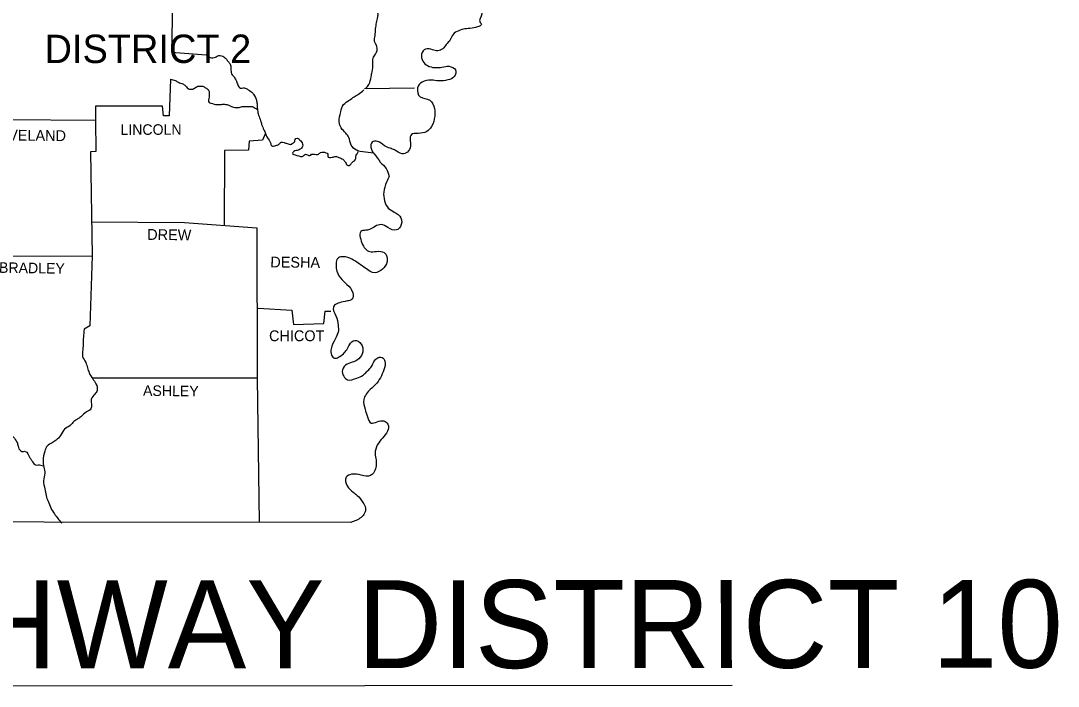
# Model space of a CAD drawing. Extents: x 2520745 to 2582119, y -1491628 to -1461664.
# Drawn here: x 2561979 to 2568174, y -1472575 to -1468600 of the extents above; entities that cross this region are included whole.
import ezdxf

# ---------------------------------------------------------------- set-up
doc = ezdxf.new("R2010")
doc.units = 0
doc.layers.add('R_Draft', color=7, linetype='Continuous')

msp = doc.modelspace()

# ---------------------------------------------------------------- linework, layer by layer
at = {"layer": 'R_Draft'}
for p, q in [((2564031, -1469004.7), (2564331, -1469000)), ((2563384.5, -1469125.1), (2563393.1, -1469130)), ((2564085.2, -1469391.7), (2563990.7, -1469379.7)), ((2556309, -1472574.9), (2566227.4, -1472568.9))]:
    msp.add_line(p, q, dxfattribs=at)
for points in [[(2562891, -1468199.2), (2562878.8, -1468787.9), (2563087.3, -1468804.3)], [(2562874.4, -1468948.4), (2562865.6, -1469168.9), (2562831.1, -1469168.9), (2562825, -1469110.4), (2562426, -1469110.7), (2562426.1, -1469194.7)], [(2561892.1, -1469190.5), (2562423.1, -1469193.2)], [(2562426.1, -1469193.2), (2562427.7, -1469380.7), (2562396.2, -1469382.2), (2562405.6, -1470004.7)], [(2563440.1, -1469272.1), (2563422.1, -1469312.6), (2563342.6, -1469320.1), (2563338.2, -1469374.1), (2563195.7, -1469374.2), (2563194.5, -1469822.8)], [(2562400.9, -1469800.7), (2562957.4, -1469804.9), (2563389.5, -1469837.6)], [(2563389.5, -1469837.6), (2563390, -1470734.6), (2563402.5, -1471597.1)], [(2561727.6, -1470006.6), (2562405.6, -1470004.7)], [(2562405.6, -1470004.7), (2562390.8, -1470421.7), (2562357.8, -1470442.7)], [(2563397.3, -1470316.1), (2563598.3, -1470328), (2563607.3, -1470415), (2563788.8, -1470408.9), (2563796.3, -1470335.4), (2563830.8, -1470335.3)], [(2563950, -1471596.8), (2558452.5, -1471591.1), (2558448.8, -1470377.6)], [(2562405.4, -1470733.7), (2563390, -1470733.1)]]:
    msp.add_lwpolyline(points, dxfattribs=at)
for points in [[(2565210.6, -1467544.5), (2565176.1, -1467588), (2565125.1, -1467561), (2565125.1, -1467525), (2565132.5, -1467487.5), (2565114.5, -1467463.5), (2565083, -1467474.1), (2565083.1, -1467520.6), (2565080.1, -1467565.6), (2565071.1, -1467630.1), (2565092.1, -1467649.6), (2565140.1, -1467655.5), (2565174.6, -1467664.5), (2565195.7, -1467699), (2565194.2, -1467741), (2565177.7, -1467781.5), (2565153.7, -1467814.5), (2565116.2, -1467826.5), (2565086.2, -1467807.1), (2565074.2, -1467768.1), (2565060.7, -1467733.6), (2565035.2, -1467708.1), (2565008.2, -1467736.6), (2565002.2, -1467789.1), (2565003.7, -1467834.1), (2565003.8, -1467895.6), (2565042.8, -1467936.1), (2565066.8, -1467982.6), (2565059.4, -1468024.6), (2565030.9, -1468074.1), (2565018.9, -1468117.6), (2565007, -1468176.1), (2565008.5, -1468240.6), (2564998, -1468303.6), (2564977.1, -1468345.6), (2564938.1, -1468380.2), (2564912.6, -1468402.7), (2564891.6, -1468425.2), (2564881.1, -1468470.2), (2564873.7, -1468501.7), (2564845.2, -1468539.2), (2564822.7, -1468542.2), (2564804.7, -1468527.2), (2564798.7, -1468501.7), (2564798.6, -1468476.2), (2564786.6, -1468450.7), (2564749.1, -1468440.3), (2564719.1, -1468441.8), (2564705.6, -1468462.8), (2564725.2, -1468521.3), (2564732.7, -1468558.8), (2564722.2, -1468609.8), (2564728.2, -1468615.8), (2564674.2, -1468644.3), (2564630.7, -1468648.8), (2564594.7, -1468659.4), (2564560.3, -1468681.9), (2564543.8, -1468714.9), (2564519.8, -1468741.9), (2564498.8, -1468767.4), (2564470.3, -1468779.4), (2564438.8, -1468773.5), (2564396.8, -1468769), (2564372.8, -1468799), (2564380.4, -1468842.5), (2564408.9, -1468868), (2564450.9, -1468880), (2564494.4, -1468876.9), (2564536.4, -1468872.4), (2564575.4, -1468893.4), (2564567.9, -1468933.9), (2564530.4, -1468953.4), (2564474.9, -1468959.4), (2564429.9, -1468955), (2564375.9, -1468967), (2564349, -1469001.5), (2564364, -1469054), (2564422.5, -1469075), (2564449.5, -1469124.5), (2564451.1, -1469171), (2564431.6, -1469232.5), (2564404.6, -1469261), (2564352.1, -1469273), (2564311.6, -1469280.5), (2564305.7, -1469349.5), (2564287.7, -1469384.1), (2564256.2, -1469394.6), (2564211.2, -1469372.1), (2564184.2, -1469361.6), (2564151.2, -1469346.6), (2564109.1, -1469321.2), (2564077.7, -1469325.7), (2564086.7, -1469391.7), (2564089.7, -1469394.7), (2564125.7, -1469444.2), (2564161.7, -1469483.1), (2564178.3, -1469529.6)], [(2565210.6, -1467544.5), (2565176.1, -1467588), (2565125.1, -1467561), (2565125.1, -1467525), (2565132.5, -1467487.5), (2565114.5, -1467463.5), (2565083, -1467474.1), (2565083.1, -1467520.6), (2565080.1, -1467565.6), (2565071.1, -1467630.1), (2565092.1, -1467649.6), (2565140.1, -1467655.5), (2565174.6, -1467664.5), (2565195.7, -1467699), (2565194.2, -1467741), (2565177.7, -1467781.5), (2565153.7, -1467814.5), (2565116.2, -1467826.5), (2565086.2, -1467807.1), (2565074.2, -1467768.1), (2565060.7, -1467733.6), (2565035.2, -1467708.1), (2565008.2, -1467736.6), (2565002.2, -1467789.1), (2565003.7, -1467834.1), (2565003.8, -1467895.6), (2565042.8, -1467936.1), (2565066.8, -1467982.6), (2565059.4, -1468024.6), (2565030.9, -1468074.1), (2565018.9, -1468117.6), (2565007, -1468176.1), (2565008.5, -1468240.6), (2564998, -1468303.6), (2564977.1, -1468345.6), (2564938.1, -1468380.2), (2564912.6, -1468402.7), (2564891.6, -1468425.2), (2564881.1, -1468470.2), (2564873.7, -1468501.7), (2564845.2, -1468539.2), (2564822.7, -1468542.2), (2564804.7, -1468527.2), (2564798.7, -1468501.7), (2564798.6, -1468476.2), (2564786.6, -1468450.7), (2564749.1, -1468440.3), (2564719.1, -1468441.8), (2564705.6, -1468462.8), (2564725.2, -1468521.3), (2564732.7, -1468558.8), (2564722.2, -1468609.8), (2564728.2, -1468615.8), (2564674.2, -1468644.3), (2564630.7, -1468648.8), (2564594.7, -1468659.4), (2564560.3, -1468681.9), (2564543.8, -1468714.9), (2564519.8, -1468741.9), (2564498.8, -1468767.4), (2564470.3, -1468779.4), (2564438.8, -1468773.5), (2564396.8, -1468769), (2564372.8, -1468799), (2564380.4, -1468842.5), (2564408.9, -1468868), (2564450.9, -1468880), (2564494.4, -1468876.9), (2564536.4, -1468872.4), (2564575.4, -1468893.4), (2564567.9, -1468933.9), (2564530.4, -1468953.4), (2564474.9, -1468959.4), (2564429.9, -1468955), (2564375.9, -1468967), (2564349, -1469001.5), (2564364, -1469054), (2564422.5, -1469075), (2564449.5, -1469124.5), (2564451.1, -1469171), (2564431.6, -1469232.5), (2564404.6, -1469261), (2564352.1, -1469273), (2564311.6, -1469280.5), (2564305.7, -1469349.5), (2564287.7, -1469384.1), (2564256.2, -1469394.6), (2564211.2, -1469372.1), (2564184.2, -1469361.6), (2564151.2, -1469346.6), (2564109.1, -1469321.2), (2564077.7, -1469325.7), (2564086.7, -1469391.7), (2564089.7, -1469394.7), (2564125.7, -1469444.2), (2564161.7, -1469483.1), (2564178.3, -1469529.6)], [(2564038.5, -1469004.7), (2564057.9, -1468980.7), (2564071.4, -1468934.2), (2564077.4, -1468905.7), (2564081.9, -1468856.2), (2564083.3, -1468823.2), (2564098.3, -1468799.2), (2564105.8, -1468754.2), (2564092.3, -1468724.2), (2564095.3, -1468688.2), (2564098.2, -1468647.7), (2564104.2, -1468611.7), (2564111.7, -1468577.2), (2564111.7, -1468554.7), (2564092.2, -1468524.7), (2564062.2, -1468505.2), (2564038.1, -1468497.7), (2564023.1, -1468487.2), (2564002.1, -1468469.2), (2563981.1, -1468433.2), (2563969.1, -1468419.7), (2563945.1, -1468388.3), (2563921.1, -1468370.3), (2563906, -1468329.8), (2563882, -1468301.3), (2563849, -1468289.3), (2563825, -1468263.8), (2563816, -1468224.8), (2563801, -1468200.8), (2563780, -1468185.9), (2563745.4, -1468164.9), (2563719.9, -1468149.9), (2563712.4, -1468115.4), (2563697.4, -1468098.9), (2563661.4, -1468089.9), (2563656.9, -1468028.4)], [(2563087.3, -1468804.3), (2563109.8, -1468819.3), (2563141.3, -1468817.8), (2563162.3, -1468808.7), (2563178.8, -1468810.2), (2563201.3, -1468823.7), (2563216.4, -1468841.7), (2563226.9, -1468855.2), (2563234.4, -1468876.2), (2563234.4, -1468895.7), (2563241.9, -1468922.7), (2563250.9, -1468933.2), (2563262.9, -1468952.7), (2563270.4, -1468970.7), (2563274.9, -1468982.7), (2563291.5, -1469002.2), (2563306.5, -1469000.7), (2563320, -1469002.1), (2563338, -1469012.6), (2563365, -1469033.6), (2563369.5, -1469039.6), (2563387.5, -1469078.6), (2563390.5, -1469102.6), (2563393.5, -1469134.1), (2563399.6, -1469164.1), (2563411.6, -1469197.1), (2563417.6, -1469219.6), (2563431.1, -1469251.1), (2563440.1, -1469272.1), (2563452.1, -1469299.1), (2563470.2, -1469329.1), (2563477.7, -1469347), (2563503.2, -1469345.5), (2563521.2, -1469338), (2563534.7, -1469326), (2563551.2, -1469327.5), (2563569.2, -1469333.5), (2563593.2, -1469338), (2563608.2, -1469329), (2563615.7, -1469323), (2563617.1, -1469309.5), (2563630.6, -1469302), (2563645.6, -1469312.4), (2563662.2, -1469336.4), (2563662.2, -1469351.4), (2563656.2, -1469360.4), (2563636.7, -1469372.5), (2563609.7, -1469381.5), (2563602.2, -1469392), (2563627.7, -1469404), (2563668.2, -1469406.9), (2563678.7, -1469397.9), (2563705.7, -1469405.4), (2563716.2, -1469397.9), (2563752.2, -1469399.4), (2563768.7, -1469387.4), (2563801.7, -1469388.8), (2563812.2, -1469396.3), (2563812.2, -1469409.8), (2563839.2, -1469415.8), (2563858.7, -1469411.3), (2563884.2, -1469418.8), (2563906.7, -1469430.8), (2563918.7, -1469447.3), (2563933.7, -1469465.3), (2563947.2, -1469460.8), (2563957.7, -1469447.3), (2563980.2, -1469423.2), (2563980.2, -1469408.2), (2563986.2, -1469397.7), (2563993.7, -1469382.7)], [(2562874.4, -1468948.4), (2562901.4, -1468957.4), (2562920.9, -1468967.9), (2562946.4, -1468976.9), (2562962.9, -1468988.9), (2562985.5, -1469008.3), (2563012.5, -1469005.3), (2563031.9, -1468993.3), (2563051.4, -1468990.3), (2563066.4, -1468991.8), (2563083, -1469000.8), (2563101, -1469014.3), (2563104, -1469033.8), (2563104, -1469056.3), (2563104, -1469087.8), (2563114.5, -1469092.3), (2563152, -1469101.2), (2563177.5, -1469099.7), (2563201.5, -1469099.7), (2563221, -1469104.2), (2563237.5, -1469113.2), (2563249.5, -1469116.2), (2563267.5, -1469119.2), (2563282.5, -1469117.7), (2563308, -1469111.7), (2563323, -1469111.6), (2563347, -1469111.6), (2563362, -1469113.1), (2563384.5, -1469125.1)], [(2563995.2, -1469378.2), (2563984.7, -1469373.7), (2563951.7, -1469342.3), (2563938.1, -1469297.3), (2563920.1, -1469271.8), (2563893.1, -1469240.3), (2563881.1, -1469204.3), (2563890, -1469144.3), (2563906.5, -1469100.8), (2563941, -1469075.3), (2563969.5, -1469054.2), (2563996.5, -1469039.2), (2564028, -1469013.7)], [(2564178.3, -1469529.6), (2564163.3, -1469564.1), (2564146.8, -1469624.1), (2564151.4, -1469675.1), (2564173.9, -1469718.6), (2564209.9, -1469742.6), (2564248.9, -1469777.1), (2564246, -1469829.6), (2564223.5, -1469849.1), (2564171, -1469835.6), (2564130.5, -1469817.6), (2564096, -1469828.2), (2564049.5, -1469850.7), (2564015, -1469855.2), (2564016.5, -1469927.2), (2564063.1, -1469978.2), (2564103.6, -1469978.2), (2564150.1, -1469984.1), (2564166.6, -1470038.1), (2564139.6, -1470083.1), (2564094.6, -1470105.7), (2564037.6, -1470078.7), (2563997.1, -1470050.2), (2563956.6, -1470023.3), (2563905.6, -1470009.8), (2563877.1, -1470015.8), (2563863.6, -1470078.8), (2563887.6, -1470135.8), (2563926.7, -1470174.8), (2563962.7, -1470225.8), (2563956.7, -1470263.3), (2563929.7, -1470273.8), (2563881.7, -1470284.3), (2563853.2, -1470299.3), (2563845.8, -1470311.3), (2563860.8, -1470362.3), (2563874.3, -1470417.8), (2563874.3, -1470459.8), (2563857.9, -1470498.8), (2563832.4, -1470558.8), (2563835.4, -1470597.8), (2563853.4, -1470615.8), (2563875.9, -1470609.8), (2563905.9, -1470588.8), (2563925.4, -1470564.8), (2563941.9, -1470534.8), (2563973.4, -1470509.2), (2564012.4, -1470531.7), (2564021.4, -1470578.2), (2563998.9, -1470618.7), (2563967.5, -1470636.7), (2563928.5, -1470651.8), (2563900, -1470684.8), (2563907.5, -1470723.8), (2563930, -1470744.8), (2563985.5, -1470734.2), (2564023, -1470717.7), (2564044, -1470696.7), (2564069.5, -1470671.2), (2564083, -1470645.7), (2564102.4, -1470618.7), (2564136.9, -1470611.1), (2564153.4, -1470633.6), (2564147.5, -1470684.6), (2564126.5, -1470732.7), (2564098, -1470773.2), (2564066.6, -1470801.7), (2564027.6, -1470863.2), (2564035.1, -1470920.2), (2564050.2, -1470966.7), (2564071.2, -1471002.7), (2564107.2, -1470995.2), (2564147.7, -1470990.6), (2564171.7, -1471010.1), (2564168.7, -1471052.1), (2564138.7, -1471092.6), (2564110.3, -1471131.7), (2564095.3, -1471185.7), (2564101.3, -1471223.2), (2564101.3, -1471257.7), (2564089.4, -1471295.2), (2564068.4, -1471316.2), (2564012.9, -1471314.7), (2563954.4, -1471308.8), (2563922.9, -1471326.8), (2563928.9, -1471377.8), (2563963.4, -1471415.3), (2563987.4, -1471434.7), (2564022, -1471476.7), (2564037, -1471511.2), (2564032.5, -1471541.2), (2564011.5, -1471566.7), (2563950, -1471596.8)], [(2564178.3, -1469529.6), (2564163.3, -1469564.1), (2564146.8, -1469624.1), (2564151.4, -1469675.1), (2564173.9, -1469718.6), (2564209.9, -1469742.6), (2564248.9, -1469777.1), (2564246, -1469829.6), (2564223.5, -1469849.1), (2564171, -1469835.6), (2564130.5, -1469817.6), (2564096, -1469828.2), (2564049.5, -1469850.7), (2564015, -1469855.2), (2564016.5, -1469927.2), (2564063.1, -1469978.2), (2564103.6, -1469978.2), (2564150.1, -1469984.1), (2564166.6, -1470038.1), (2564139.6, -1470083.1), (2564094.6, -1470105.7), (2564037.6, -1470078.7), (2563997.1, -1470050.2), (2563956.6, -1470023.3), (2563905.6, -1470009.8), (2563877.1, -1470015.8), (2563863.6, -1470078.8), (2563887.6, -1470135.8), (2563926.7, -1470174.8), (2563962.7, -1470225.8), (2563956.7, -1470263.3), (2563929.7, -1470273.8), (2563881.7, -1470284.3), (2563853.2, -1470299.3), (2563845.8, -1470311.3), (2563860.8, -1470362.3), (2563874.3, -1470417.8), (2563874.3, -1470459.8), (2563857.9, -1470498.8), (2563832.4, -1470558.8), (2563835.4, -1470597.8), (2563853.4, -1470615.8), (2563875.9, -1470609.8), (2563905.9, -1470588.8), (2563925.4, -1470564.8), (2563941.9, -1470534.8), (2563973.4, -1470509.2), (2564012.4, -1470531.7), (2564021.4, -1470578.2), (2563998.9, -1470618.7), (2563967.5, -1470636.7), (2563928.5, -1470651.8), (2563900, -1470684.8), (2563907.5, -1470723.8), (2563930, -1470744.8), (2563985.5, -1470734.2), (2564023, -1470717.7), (2564044, -1470696.7), (2564069.5, -1470671.2), (2564083, -1470645.7), (2564102.4, -1470618.7), (2564136.9, -1470611.1), (2564153.4, -1470633.6), (2564147.5, -1470684.6), (2564126.5, -1470732.7), (2564098, -1470773.2), (2564066.6, -1470801.7), (2564027.6, -1470863.2), (2564035.1, -1470920.2), (2564050.2, -1470966.7), (2564071.2, -1471002.7), (2564107.2, -1470995.2), (2564147.7, -1470990.6), (2564171.7, -1471010.1), (2564168.7, -1471052.1), (2564138.7, -1471092.6), (2564110.3, -1471131.7), (2564095.3, -1471185.7), (2564101.3, -1471223.2), (2564101.3, -1471257.7), (2564089.4, -1471295.2), (2564068.4, -1471316.2), (2564012.9, -1471314.7), (2563954.4, -1471308.8), (2563922.9, -1471326.8), (2563928.9, -1471377.8), (2563963.4, -1471415.3), (2563987.4, -1471434.7), (2564022, -1471476.7), (2564037, -1471511.2), (2564032.5, -1471541.2), (2564011.5, -1471566.7), (2563950, -1471596.8)], [(2562357.8, -1470442.7), (2562353.4, -1470489.2), (2562351.9, -1470532.7), (2562348.9, -1470574.7), (2562348.9, -1470606.2), (2562367, -1470640.7), (2562377.5, -1470673.7), (2562388, -1470702.2), (2562409, -1470739.7), (2562428.5, -1470768.2), (2562434.6, -1470808.7), (2562422.6, -1470829.7), (2562400.1, -1470861.2), (2562398.6, -1470918.2), (2562371.6, -1470936.2), (2562337.2, -1470966.2), (2562317.7, -1470979.8), (2562296.7, -1470993.3), (2562274.2, -1471017.3), (2562241.2, -1471039.8), (2562217.2, -1471077.3), (2562190.2, -1471105.8), (2562167.7, -1471120.8), (2562136.3, -1471140.4), (2562122.8, -1471170.4), (2562112.3, -1471225.9), (2562116.8, -1471266.4), (2562122.9, -1471302.4), (2562115.4, -1471347.4), (2562122.9, -1471396.9), (2562130.4, -1471435.9), (2562142.5, -1471470.4), (2562159, -1471509.4), (2562180, -1471545.3), (2562225, -1471600.8)], [(2560862.5, -1470790.1), (2560886.5, -1470773.6), (2560909, -1470764.6), (2560931.5, -1470769.1), (2560955.5, -1470772.1), (2560976.5, -1470769.1), (2561003.5, -1470773.6), (2561026, -1470787), (2561051.5, -1470797.5), (2561077, -1470797.5), (2561099.5, -1470797.5), (2561119.1, -1470811), (2561155.1, -1470809.5), (2561185, -1470797.4), (2561215, -1470788.4), (2561255.5, -1470783.9), (2561291.6, -1470809.4), (2561317.1, -1470830.4), (2561338.1, -1470854.4), (2561353.1, -1470881.3), (2561369.6, -1470896.3), (2561396.6, -1470906.8), (2561417.6, -1470911.3), (2561443.1, -1470918.8), (2561456.6, -1470924.8), (2561468.6, -1470953.3), (2561488.2, -1470992.3), (2561525.7, -1471005.7), (2561572.2, -1470987.7), (2561609.7, -1470977.2), (2561636.7, -1470968.2), (2561653.1, -1470962.2), (2561668.1, -1470960.7), (2561663.6, -1470957.7), (2561681.6, -1470953.1), (2561698.2, -1470965.1), (2561708.7, -1470981.6), (2561726.7, -1471005.6), (2561743.2, -1471026.6), (2561759.7, -1471034.1), (2561776.2, -1471025.1), (2561798.7, -1471032.6), (2561818.2, -1471040.1), (2561840.7, -1471046), (2561860.2, -1471047.5), (2561885.7, -1471053.5), (2561905.2, -1471064), (2561923.2, -1471074.5), (2561941.2, -1471094), (2561959.2, -1471124), (2561965.3, -1471148), (2561986.3, -1471172), (2562005.8, -1471171.9), (2562034.3, -1471210.9), (2562044.8, -1471225.9), (2562067.3, -1471252.9), (2562083.8, -1471252.9), (2562115.3, -1471258.9)]]:
    msp.add_spline(points, degree=3, dxfattribs=at)

# ---------------------------------------------------------------- texts
for s, height, rotation, p in [('DISTRICT 2', 169.5, 0.03494, (2562121.4, -1468852.9)), ('CLEVELAND', 64.51, 359.37259, (2561736.1, -1469313.6)), ('LINCOLN', 63, 0.03494, (2562574.6, -1469281.6)), ('DREW', 64.49, 359.26072, (2562734, -1469908.5)), ('BRADLEY', 62.99, 359.17984, (2561849.1, -1470105.5)), ('DESHA', 64.49, 359.40534, (2563469.1, -1470073.1)), ('CHICOT', 64.5, 0.03494, (2563461.9, -1470514.1)), ('ASHLEY', 63.01, 359.27104, (2562709.1, -1470840)), ('ARKANSAS HIGHWAY DISTRICT 10', 525, 0.03494, (2556420.9, -1472471.4))]:
    msp.add_text(s, height=height, rotation=rotation, dxfattribs=at).set_placement(p)

doc.saveas('drawing.dxf')
